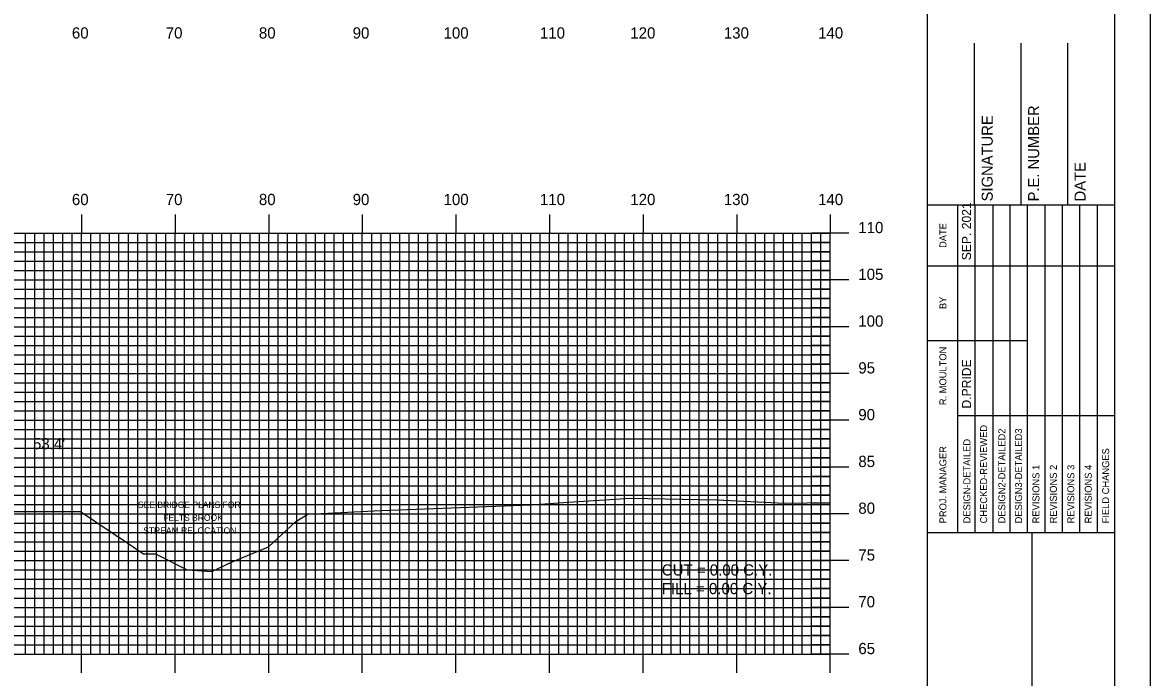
# Model space of a CAD drawing. Extents: x 857504 to 857847, y 364765 to 364985.
# Drawn here: x 857723 to 857843.5, y 364845.8 to 364915.8 of the extents above; entities that cross this region are included whole.
import ezdxf

# ---------------------------------------------------------------- set-up
doc = ezdxf.new("R2010")
doc.units = 0
for name, color, linetype in [('ANNOTATION', 7, 'Continuous'), ('BORDER', 7, 'Continuous'), ('D_Text_Standard', 7, 'Continuous'), ('H_V ANNOTATION', 7, 'Continuous'), ('MAJOR', 7, 'Continuous'), ('MINOR', 7, 'Continuous'), ('PLOT BOUNDARY', 7, 'Continuous'), ('S_Roadway_Centerline', 7, 'Continuous')]:
    doc.layers.add(name, color=color, linetype=linetype)

msp = doc.modelspace()

# ---------------------------------------------------------------- linework, layer by layer
at = {"layer": 'BORDER'}
for p, q in [((857819.71, 364771.3), (857819.71, 364981.3)), ((857824.71, 364896.31), (857824.71, 364913.6)), ((857829.71, 364896.31), (857829.71, 364913.6)), ((857834.71, 364896.31), (857834.71, 364913.6)), ((857819.71, 364896.31), (857839.71, 364896.31)), ((857819.71, 364861.31), (857839.71, 364861.31)), ((857830.89, 364791.31), (857830.89, 364861.31))]:
    msp.add_line(p, q, dxfattribs=at)
msp.add_lwpolyline([(857519.71, 364771.3), (857839.71, 364771.3), (857839.71, 364981.3), (857519.71, 364981.3)], close=True, dxfattribs=at)
for points in [[(857822.94, 364889.81), (857822.94, 364896.31)], [(857824.8, 364861.31), (857824.8, 364896.31)], [(857826.67, 364896.31), (857826.67, 364861.31)], [(857828.53, 364861.31), (857828.53, 364896.31)], [(857830.39, 364861.31), (857830.39, 364896.31)], [(857832.26, 364861.31), (857832.26, 364896.31)], [(857834.12, 364861.31), (857834.12, 364896.31)], [(857835.98, 364861.31), (857835.98, 364896.31)], [(857837.85, 364861.31), (857837.85, 364896.31)], [(857822.94, 364861.31), (857822.94, 364894.9)], [(857819.71, 364889.81), (857839.71, 364889.81)], [(857819.71, 364881.81), (857822.94, 364881.81)], [(857822.94, 364881.81), (857830.39, 364881.81)], [(857822.94, 364873.81), (857839.71, 364873.81)]]:
    msp.add_lwpolyline(points, dxfattribs=at)
at = {"layer": 'MAJOR'}
for p, q in [((857729.31, 364895.31), (857729.31, 364893.3)), ((857739.31, 364895.31), (857739.31, 364893.3)), ((857749.31, 364895.31), (857749.31, 364893.3)), ((857759.31, 364895.31), (857759.31, 364893.3)), ((857769.31, 364895.31), (857769.31, 364893.3)), ((857779.31, 364895.31), (857779.31, 364893.3)), ((857789.31, 364895.31), (857789.31, 364893.3)), ((857799.31, 364895.31), (857799.31, 364893.3)), ((857809.31, 364895.31), (857809.31, 364893.3)), ((857529.31, 364893.3), (857809.31, 364893.3)), ((857529.31, 364893.3), (857809.31, 364893.3)), ((857729.31, 364848.3), (857729.31, 364893.3)), ((857739.31, 364848.3), (857739.31, 364893.3)), ((857749.31, 364848.3), (857749.31, 364893.3)), ((857759.31, 364848.3), (857759.31, 364893.3)), ((857769.31, 364848.3), (857769.31, 364893.3)), ((857779.31, 364848.3), (857779.31, 364893.3)), ((857789.31, 364848.3), (857789.31, 364893.3)), ((857799.31, 364848.3), (857799.31, 364893.3)), ((857811.31, 364893.3), (857807.3, 364893.3)), ((857809.31, 364848.3), (857809.31, 364893.3)), ((857809.31, 364848.3), (857809.31, 364893.3)), ((857529.31, 364888.3), (857809.31, 364888.3)), ((857811.31, 364888.3), (857807.3, 364888.3)), ((857529.31, 364883.3), (857809.31, 364883.3)), ((857811.31, 364883.3), (857807.3, 364883.3)), ((857529.31, 364878.3), (857809.31, 364878.3)), ((857811.31, 364878.3), (857807.3, 364878.3)), ((857529.31, 364873.3), (857809.31, 364873.3)), ((857811.31, 364873.3), (857807.3, 364873.3)), ((857529.31, 364868.3), (857809.31, 364868.3)), ((857811.31, 364868.3), (857807.3, 364868.3)), ((857529.31, 364863.3), (857809.31, 364863.3)), ((857811.31, 364863.3), (857807.3, 364863.3)), ((857529.31, 364858.3), (857809.31, 364858.3)), ((857811.31, 364858.3), (857807.3, 364858.3)), ((857529.31, 364853.3), (857809.31, 364853.3)), ((857811.31, 364853.3), (857807.3, 364853.3)), ((857529.31, 364848.3), (857809.31, 364848.3)), ((857529.31, 364848.3), (857809.31, 364848.3)), ((857729.31, 364846.3), (857729.31, 364848.3)), ((857739.31, 364846.3), (857739.31, 364848.3)), ((857749.31, 364846.3), (857749.31, 364848.3)), ((857759.31, 364846.3), (857759.31, 364848.3)), ((857769.31, 364846.3), (857769.31, 364848.3)), ((857779.31, 364846.3), (857779.31, 364848.3)), ((857789.31, 364846.3), (857789.31, 364848.3)), ((857799.31, 364846.3), (857799.31, 364848.3)), ((857811.31, 364848.3), (857807.3, 364848.3)), ((857809.31, 364846.3), (857809.31, 364848.3))]:
    msp.add_line(p, q, dxfattribs=at)
at = {"layer": 'MINOR'}
for p, q in [((857529.31, 364892.3), (857809.31, 364892.3)), ((857723.31, 364848.3), (857723.31, 364893.3)), ((857724.31, 364848.3), (857724.31, 364893.3)), ((857725.31, 364848.3), (857725.31, 364893.3)), ((857726.31, 364848.3), (857726.31, 364893.3)), ((857727.31, 364848.3), (857727.31, 364893.3)), ((857728.31, 364848.3), (857728.31, 364893.3)), ((857730.31, 364848.3), (857730.31, 364893.3)), ((857731.31, 364848.3), (857731.31, 364893.3)), ((857732.31, 364848.3), (857732.31, 364893.3)), ((857733.31, 364848.3), (857733.31, 364893.3)), ((857734.31, 364848.3), (857734.31, 364893.3)), ((857735.31, 364848.3), (857735.31, 364893.3)), ((857736.31, 364848.3), (857736.31, 364893.3)), ((857737.31, 364848.3), (857737.31, 364893.3)), ((857738.31, 364848.3), (857738.31, 364893.3)), ((857740.31, 364848.3), (857740.31, 364893.3)), ((857741.31, 364848.3), (857741.31, 364893.3)), ((857742.31, 364848.3), (857742.31, 364893.3)), ((857743.31, 364848.3), (857743.31, 364893.3)), ((857744.31, 364848.3), (857744.31, 364893.3)), ((857745.31, 364848.3), (857745.31, 364893.3)), ((857746.31, 364848.3), (857746.31, 364893.3)), ((857747.31, 364848.3), (857747.31, 364893.3)), ((857748.31, 364848.3), (857748.31, 364893.3)), ((857750.31, 364848.3), (857750.31, 364893.3)), ((857751.31, 364848.3), (857751.31, 364893.3)), ((857752.31, 364848.3), (857752.31, 364893.3)), ((857753.31, 364848.3), (857753.31, 364893.3)), ((857754.31, 364848.3), (857754.31, 364893.3)), ((857755.31, 364848.3), (857755.31, 364893.3)), ((857756.31, 364848.3), (857756.31, 364893.3)), ((857757.31, 364848.3), (857757.31, 364893.3)), ((857758.31, 364848.3), (857758.31, 364893.3)), ((857760.31, 364848.3), (857760.31, 364893.3)), ((857761.31, 364848.3), (857761.31, 364893.3)), ((857762.31, 364848.3), (857762.31, 364893.3)), ((857763.31, 364848.3), (857763.31, 364893.3)), ((857764.31, 364848.3), (857764.31, 364893.3)), ((857765.31, 364848.3), (857765.31, 364893.3)), ((857766.31, 364848.3), (857766.31, 364893.3)), ((857767.31, 364848.3), (857767.31, 364893.3)), ((857768.31, 364848.3), (857768.31, 364893.3)), ((857770.31, 364848.3), (857770.31, 364893.3)), ((857771.31, 364848.3), (857771.31, 364893.3)), ((857772.31, 364848.3), (857772.31, 364893.3)), ((857773.31, 364848.3), (857773.31, 364893.3)), ((857774.31, 364848.3), (857774.31, 364893.3)), ((857775.31, 364848.3), (857775.31, 364893.3)), ((857776.31, 364848.3), (857776.31, 364893.3)), ((857777.31, 364848.3), (857777.31, 364893.3)), ((857778.31, 364848.3), (857778.31, 364893.3)), ((857780.31, 364848.3), (857780.31, 364893.3)), ((857781.31, 364848.3), (857781.31, 364893.3)), ((857782.31, 364848.3), (857782.31, 364893.3)), ((857783.31, 364848.3), (857783.31, 364893.3)), ((857784.31, 364848.3), (857784.31, 364893.3)), ((857785.31, 364848.3), (857785.31, 364893.3)), ((857786.31, 364848.3), (857786.31, 364893.3)), ((857787.31, 364848.3), (857787.31, 364893.3)), ((857788.31, 364848.3), (857788.31, 364893.3)), ((857790.31, 364848.3), (857790.31, 364893.3)), ((857791.31, 364848.3), (857791.31, 364893.3)), ((857792.31, 364848.3), (857792.31, 364893.3)), ((857793.31, 364848.3), (857793.31, 364893.3)), ((857794.31, 364848.3), (857794.31, 364893.3)), ((857795.31, 364848.3), (857795.31, 364893.3)), ((857796.31, 364848.3), (857796.31, 364893.3)), ((857797.31, 364848.3), (857797.31, 364893.3)), ((857798.31, 364848.3), (857798.31, 364893.3)), ((857800.31, 364848.3), (857800.31, 364893.3)), ((857801.31, 364848.3), (857801.31, 364893.3)), ((857802.31, 364848.3), (857802.31, 364893.3)), ((857803.31, 364848.3), (857803.31, 364893.3)), ((857804.31, 364848.3), (857804.31, 364893.3)), ((857805.31, 364848.3), (857805.31, 364893.3)), ((857806.31, 364848.3), (857806.31, 364893.3)), ((857809.31, 364892.3), (857807.3, 364892.3)), ((857807.31, 364848.3), (857807.31, 364893.3)), ((857808.31, 364848.3), (857808.31, 364893.3)), ((857529.31, 364891.3), (857809.31, 364891.3)), ((857809.31, 364891.3), (857807.3, 364891.3)), ((857529.31, 364890.3), (857809.31, 364890.3)), ((857809.31, 364890.3), (857807.3, 364890.3)), ((857529.31, 364889.3), (857809.31, 364889.3)), ((857809.31, 364889.3), (857807.3, 364889.3)), ((857529.31, 364887.3), (857809.31, 364887.3)), ((857529.31, 364886.3), (857809.31, 364886.3)), ((857809.31, 364887.3), (857807.3, 364887.3)), ((857809.31, 364886.3), (857807.3, 364886.3)), ((857529.31, 364885.3), (857809.31, 364885.3)), ((857809.31, 364885.3), (857807.3, 364885.3)), ((857529.31, 364884.3), (857809.31, 364884.3)), ((857809.31, 364884.3), (857807.3, 364884.3)), ((857529.31, 364882.3), (857809.31, 364882.3)), ((857809.31, 364882.3), (857807.3, 364882.3)), ((857529.31, 364881.3), (857809.31, 364881.3)), ((857529.31, 364880.3), (857809.31, 364880.3)), ((857809.31, 364881.3), (857807.3, 364881.3)), ((857809.31, 364880.3), (857807.3, 364880.3)), ((857529.31, 364879.3), (857809.31, 364879.3)), ((857809.31, 364879.3), (857807.3, 364879.3)), ((857529.31, 364877.3), (857809.31, 364877.3)), ((857809.31, 364877.3), (857807.3, 364877.3)), ((857529.31, 364876.3), (857809.31, 364876.3)), ((857529.31, 364875.3), (857809.31, 364875.3)), ((857809.31, 364876.3), (857807.3, 364876.3)), ((857809.31, 364875.3), (857807.3, 364875.3)), ((857529.31, 364874.3), (857809.31, 364874.3)), ((857809.31, 364874.3), (857807.3, 364874.3)), ((857529.31, 364872.3), (857809.31, 364872.3)), ((857809.31, 364872.3), (857807.3, 364872.3)), ((857529.31, 364871.3), (857809.31, 364871.3)), ((857809.31, 364871.3), (857807.3, 364871.3)), ((857529.31, 364870.3), (857809.31, 364870.3)), ((857529.31, 364869.3), (857809.31, 364869.3)), ((857809.31, 364870.3), (857807.3, 364870.3)), ((857809.31, 364869.3), (857807.3, 364869.3)), ((857529.31, 364867.3), (857809.31, 364867.3)), ((857809.31, 364867.3), (857807.3, 364867.3)), ((857529.31, 364866.3), (857809.31, 364866.3)), ((857809.31, 364866.3), (857807.3, 364866.3)), ((857529.31, 364865.3), (857809.31, 364865.3)), ((857809.31, 364865.3), (857807.3, 364865.3)), ((857529.31, 364864.3), (857809.31, 364864.3)), ((857809.31, 364864.3), (857807.3, 364864.3)), ((857529.31, 364862.3), (857809.31, 364862.3)), ((857809.31, 364862.3), (857807.3, 364862.3)), ((857529.31, 364861.3), (857809.31, 364861.3)), ((857809.31, 364861.3), (857807.3, 364861.3)), ((857529.31, 364860.3), (857809.31, 364860.3)), ((857809.31, 364860.3), (857807.3, 364860.3)), ((857529.31, 364859.3), (857809.31, 364859.3)), ((857809.31, 364859.3), (857807.3, 364859.3)), ((857529.31, 364857.3), (857809.31, 364857.3)), ((857809.31, 364857.3), (857807.3, 364857.3)), ((857529.31, 364856.3), (857809.31, 364856.3)), ((857809.31, 364856.3), (857807.3, 364856.3)), ((857529.31, 364855.3), (857809.31, 364855.3)), ((857809.31, 364855.3), (857807.3, 364855.3)), ((857529.31, 364854.3), (857809.31, 364854.3)), ((857809.31, 364854.3), (857807.3, 364854.3)), ((857529.31, 364852.3), (857809.31, 364852.3)), ((857529.31, 364851.3), (857809.31, 364851.3)), ((857809.31, 364852.3), (857807.3, 364852.3)), ((857809.31, 364851.3), (857807.3, 364851.3)), ((857529.31, 364850.3), (857809.31, 364850.3)), ((857809.31, 364850.3), (857807.3, 364850.3)), ((857529.31, 364849.3), (857809.31, 364849.3)), ((857809.31, 364849.3), (857807.3, 364849.3))]:
    msp.add_line(p, q, dxfattribs=at)
at = {"layer": 'PLOT BOUNDARY'}
msp.add_lwpolyline([(857503.52, 364765.18), (857843.52, 364765.18), (857843.52, 364985.18), (857503.52, 364985.18)], close=True, dxfattribs=at)
at = {"layer": 'S_Roadway_Centerline'}
msp.add_lwpolyline([(857718.85, 364863.53), (857729.19, 364863.55), (857732.59, 364861.25), (857733.91, 364860.41), (857734.84, 364859.76), (857735.93, 364859.01), (857737.22, 364859.02), (857740.61, 364857.31), (857743.24, 364857.15), (857745.39, 364858.17), (857749.3, 364859.77), (857752.21, 364862.47), (857753.49, 364863.26), (857761.29, 364863.64), (857777.33, 364864.26), (857781.32, 364864.55), (857787.97, 364864.98), (857797.22, 364864.78), (857804.4, 364864.45), (857809.31, 364864.5)], dxfattribs=at)

# ---------------------------------------------------------------- texts
at = {"layer": 'ANNOTATION'}
for s, p in [('SEE BRIDGE PLANS FOR', (857735.34, 364863.93)), ('FELTS BROOK ', (857738.04, 364862.55)), ('STREAM RELOCATION', (857735.9, 364861.17))]:
    msp.add_text(s, height=0.68, dxfattribs=at).set_placement(p)
at = {"layer": 'BORDER'}
for s, height, p in [('P.E. NUMBER', 1.1811, (857831.63, 364896.69)), ('SIGNATURE', 1.181, (857826.67, 364896.69)), ('DATE', 1.181, (857836.59, 364896.69)), ('SEP. 2021', 0.969, (857824.35, 364890.4)), ('DATE', 0.743, (857821.72, 364891.72)), ('BY', 0.743, (857821.72, 364885.18)), ('R. MOULTON', 0.745, (857821.72, 364874.91)), ('D.PRIDE', 0.969, (857824.35, 364874.55)), ('CHECKED-REVIEWED', 0.7455, (857826.07, 364862.28)), ('DESIGN2-DETAILED2', 0.7455, (857828.01, 364862.28)), ('DESIGN3-DETAILED3', 0.7455, (857829.8, 364862.28)), ('PROJ. MANAGER', 0.7455, (857821.72, 364862.28)), ('DESIGN-DETAILED', 0.7455, (857824.28, 364862.28)), ('FIELD CHANGES', 0.7455, (857839.11, 364862.28)), ('REVISIONS 1', 0.7455, (857831.66, 364862.28)), ('REVISIONS 2', 0.7455, (857833.52, 364862.28)), ('REVISIONS 3', 0.7455, (857835.39, 364862.28)), ('REVISIONS 4', 0.7455, (857837.25, 364862.28))]:
    msp.add_text(s, height=height, rotation=90, dxfattribs=at).set_placement(p)
at = {"layer": 'D_Text_Standard'}
for s, p in [("53.4'", (857724.12, 364870.2)), ('CUT = 0.00 C.Y.', (857791.31, 364856.7)), ('FILL = 0.00 C.Y.', (857791.31, 364854.71))]:
    msp.add_text(s, height=1.2, dxfattribs=at).set_placement(p)
at = {"layer": 'H_V ANNOTATION'}
for s, p in [('60', (857728.28, 364914.1)), ('70', (857738.31, 364914.1)), ('80', (857748.26, 364914.1)), ('90', (857758.28, 364914.1)), ('100', (857767.99, 364914.1)), ('110', (857778.29, 364914.1)), ('120', (857787.95, 364914.1)), ('130', (857797.94, 364914.1)), ('140', (857808.01, 364914.1)), ('60', (857728.28, 364896.3)), ('70', (857738.31, 364896.3)), ('80', (857748.26, 364896.3)), ('90', (857758.28, 364896.3)), ('100', (857767.99, 364896.3)), ('110', (857778.29, 364896.3)), ('120', (857787.95, 364896.3)), ('130', (857797.94, 364896.3)), ('140', (857808.01, 364896.3)), ('110', (857812.31, 364893.3)), ('105', (857812.31, 364888.3)), ('100', (857812.31, 364883.3)), ('95', (857812.31, 364878.3)), ('90', (857812.31, 364873.3)), ('85', (857812.31, 364868.3)), ('80', (857812.31, 364863.3)), ('75', (857812.31, 364858.3)), ('70', (857812.31, 364853.3)), ('65', (857812.31, 364848.3))]:
    msp.add_text(s, height=1.2, dxfattribs=at).set_placement(p)

doc.saveas('drawing.dxf')
